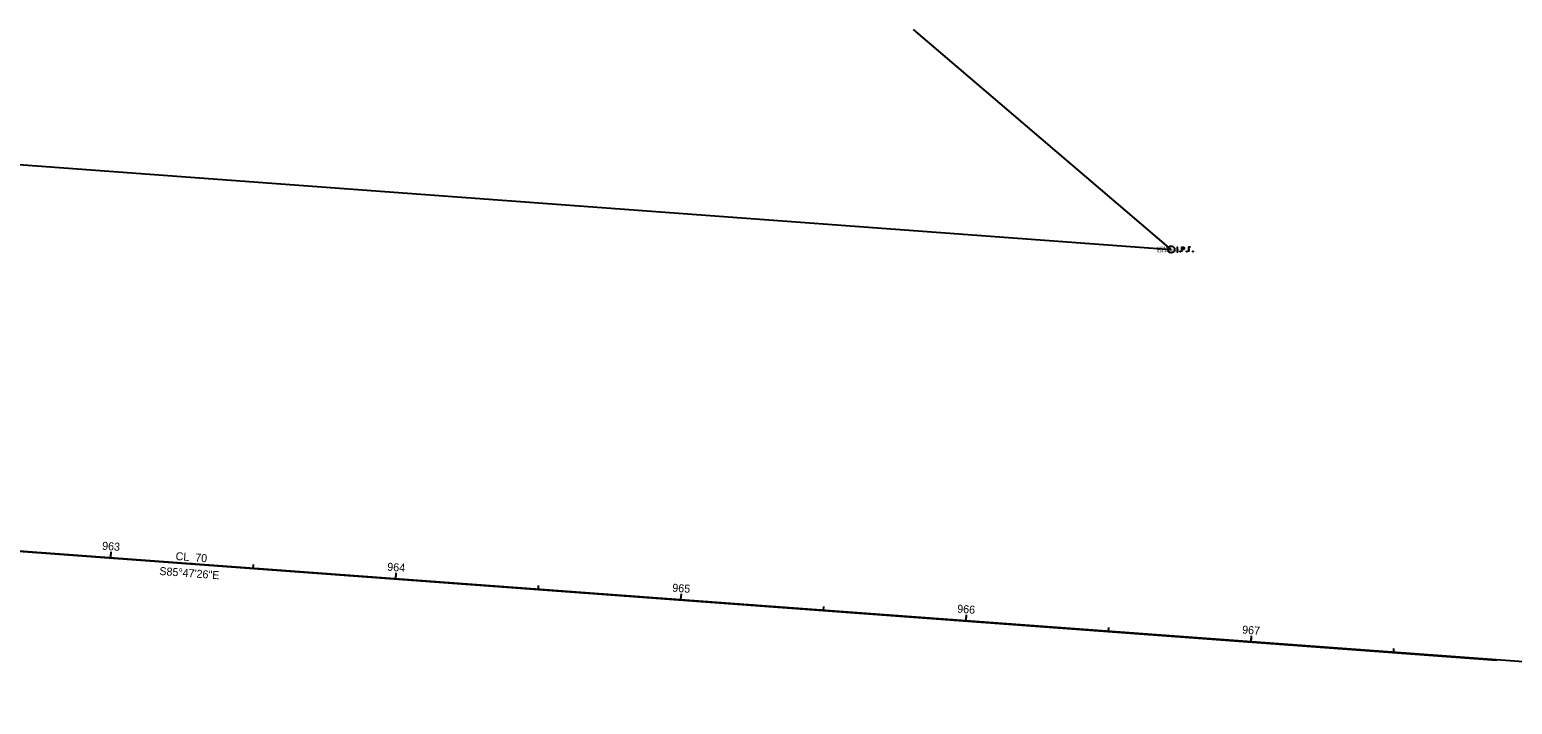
# Model space of a CAD drawing. Extents: x 1981066 to 1984208, y 708139 to 709503.
# Drawn here: x 1982974 to 1983492, y 708870 to 709106 of the extents above; entities that cross this region are included whole.
import ezdxf

# ---------------------------------------------------------------- set-up
doc = ezdxf.new("R2010")
doc.units = 0
for name, color, linetype in [('DR_X_Ditch', 7, 'Continuous'), ('DR_X_Elev_Flow', 7, 'Continuous'), ('DT_X_Break_Line', 7, 'Continuous'), ('GE_X_Cells', 7, 'Continuous'), ('LT_X_Poles', 7, 'Continuous'), ('PM_X_Dotted_Line', 7, 'Continuous'), ('PM_X_Edge_Line', 7, 'Continuous'), ('PV_P_EOP', 7, 'Continuous'), ('RD_X_Wall', 7, 'Continuous'), ('SV_X_Break_Lines', 7, 'Continuous'), ('SV_X_Shot_Marker', 7, 'Continuous'), ('SV_X_Text_Elevation', 7, 'Continuous'), ('SV_X_Text_Name', 7, 'Continuous'), ('SV_X_Toe_of_Slope', 7, 'Continuous'), ('TopoDOT_Transients', 7, 'Continuous'), ('UT_X_Misc_Cells', 7, 'Continuous')]:
    doc.layers.add(name, color=color, linetype=linetype)

msp = doc.modelspace()

# ---------------------------------------------------------------- linework, layer by layer
at = {"layer": 'DR_X_Ditch'}
msp.add_line((1982518.68, 709092.32), (1983373.1, 709029.22), dxfattribs=at)
at = {"layer": 'PM_X_Edge_Line'}
for p, q in [((1983002.13, 708921.37), (1983002.28, 708923.37)), ((1983052, 708917.7), (1983052.09, 708918.9)), ((1983101.86, 708914.03), (1983102.01, 708916.03)), ((1983151.73, 708910.36), (1983151.82, 708911.56)), ((1983201.59, 708906.69), (1983201.74, 708908.69)), ((1983251.46, 708903.02), (1983251.55, 708904.22)), ((1983301.32, 708899.35), (1983301.47, 708901.35)), ((1983351.19, 708895.68), (1983351.28, 708896.88)), ((1983401.06, 708892.01), (1983401.2, 708894.01)), ((1983450.92, 708888.34), (1983451.01, 708889.54))]:
    msp.add_line(p, q, dxfattribs=at)
at = {"layer": 'PV_P_EOP'}
msp.add_line((1983201.59, 708906.69), (1983201.68, 708907.89), dxfattribs=at)
at = {"layer": 'RD_X_Wall'}
for p, q in [((1983002.13, 708921.37), (1983002.22, 708922.57)), ((1983101.86, 708914.03), (1983101.95, 708915.23)), ((1983201.59, 708906.69), (1983201.74, 708908.69)), ((1983301.32, 708899.35), (1983301.41, 708900.55)), ((1983401.06, 708892.01), (1983401.14, 708893.21))]:
    msp.add_line(p, q, dxfattribs=at)
at = {"layer": 'SV_X_Break_Lines'}
msp.add_line((1982360.68, 708968.58), (1983700.25, 708869.99), dxfattribs=at)
at = {"layer": 'SV_X_Shot_Marker'}
for points in [[(1983375.11, 709030.02), (1983375.46, 709030.02)], [(1983375.29, 709028.42), (1983375.29, 709030.02)], [(1983376.85, 709028.42), (1983376.85, 709030.02), (1983377.38, 709030.02), (1983377.44, 709030.01), (1983377.51, 709029.98), (1983377.55, 709029.96), (1983377.58, 709029.93), (1983377.62, 709029.87), (1983377.66, 709029.81), (1983377.68, 709029.7), (1983377.68, 709029.55), (1983377.67, 709029.5), (1983377.65, 709029.43), (1983377.6, 709029.34), (1983377.56, 709029.3), (1983377.52, 709029.28), (1983377.47, 709029.25), (1983377.38, 709029.24), (1983376.85, 709029.24)], [(1983379.86, 709030.02), (1983379.1, 709030.02), (1983379.1, 709028.42)], [(1983379.1, 709029.24), (1983379.64, 709029.24)], [(1983375.11, 709028.42), (1983375.46, 709028.42)], [(1983376.25, 709028.63), (1983376.3, 709028.63), (1983376.33, 709028.61), (1983376.37, 709028.56), (1983376.37, 709028.5), (1983376.33, 709028.45), (1983376.3, 709028.42), (1983376.25, 709028.42), (1983376.21, 709028.45), (1983376.18, 709028.5), (1983376.18, 709028.56), (1983376.21, 709028.61), (1983376.25, 709028.63)], [(1983378.49, 709028.63), (1983378.55, 709028.63), (1983378.58, 709028.61), (1983378.62, 709028.56), (1983378.62, 709028.5), (1983378.58, 709028.45), (1983378.55, 709028.42), (1983378.49, 709028.42), (1983378.46, 709028.45), (1983378.43, 709028.5), (1983378.43, 709028.56), (1983378.46, 709028.61), (1983378.49, 709028.63)], [(1983380.64, 709028.63), (1983380.7, 709028.63), (1983380.73, 709028.61), (1983380.77, 709028.56), (1983380.77, 709028.5), (1983380.73, 709028.45), (1983380.7, 709028.42), (1983380.64, 709028.42), (1983380.61, 709028.45), (1983380.58, 709028.5), (1983380.58, 709028.56), (1983380.61, 709028.61), (1983380.64, 709028.63)]]:
    msp.add_lwpolyline(points, dxfattribs=at)
msp.add_circle((1983373.1, 709029.22), 1.2, dxfattribs=at)
at = {"layer": 'SV_X_Toe_of_Slope'}
msp.add_line((1983373.1, 709029.22), (1983282.92, 709106.17), dxfattribs=at)
at = {"layer": 'UT_X_Misc_Cells'}
msp.add_line((1982508.68, 708957.7), (1983486.93, 708885.45), dxfattribs=at)

# ---------------------------------------------------------------- texts
at = {"layer": 'DR_X_Elev_Flow'}
msp.add_text('914.442', height=1, dxfattribs=at).set_placement((1983368.04, 709028.22))
at = {"layer": 'DT_X_Break_Line'}
msp.add_text('CL_70', height=2.8, rotation=355.7906, dxfattribs=at).set_placement((1983024.76, 708920.53))
at = {"layer": 'GE_X_Cells'}
msp.add_text('S85°47\'26"E', height=2.8, rotation=355.7906, dxfattribs=at).set_placement((1983019.07, 708915.31))
at = {"layer": 'LT_X_Poles'}
msp.add_text('IPIN', height=1, dxfattribs=at).set_placement((1983373.1, 709028.22))
at = {"layer": 'PM_X_Dotted_Line'}
msp.add_text('S85°47\'26"E', height=2.8, rotation=355.7906, dxfattribs=at).set_placement((1983019.07, 708915.31))
at = {"layer": 'PM_X_Edge_Line'}
for s, p in [('963', (1982999.06, 708924.15)), ('964', (1983098.79, 708916.81)), ('965', (1983198.49, 708909.47)), ('966', (1983298.16, 708902.13)), ('967', (1983397.83, 708894.8))]:
    msp.add_text(s, height=2.8, rotation=355.7906, dxfattribs=at).set_placement(p)
at = {"layer": 'RD_X_Wall'}
msp.add_text('965', height=2.8, rotation=355.7906, dxfattribs=at).set_placement((1983198.49, 708909.47))
at = {"layer": 'SV_X_Text_Elevation'}
msp.add_text('CL_70', height=2.8, rotation=355.7906, dxfattribs=at).set_placement((1983024.76, 708920.53))
at = {"layer": 'SV_X_Text_Name'}
msp.add_text('CL_70', height=2.8, rotation=355.7906, dxfattribs=at).set_placement((1983024.76, 708920.53))
at = {"layer": 'TopoDOT_Transients'}
msp.add_text('S85°47\'26"E', height=2.8, rotation=355.7906, dxfattribs=at).set_placement((1983019.07, 708915.31))
at = {"layer": 'UT_X_Misc_Cells'}
msp.add_text('MON57', height=1, dxfattribs=at).set_placement((1983368.23, 709029.22))

doc.saveas('drawing.dxf')
